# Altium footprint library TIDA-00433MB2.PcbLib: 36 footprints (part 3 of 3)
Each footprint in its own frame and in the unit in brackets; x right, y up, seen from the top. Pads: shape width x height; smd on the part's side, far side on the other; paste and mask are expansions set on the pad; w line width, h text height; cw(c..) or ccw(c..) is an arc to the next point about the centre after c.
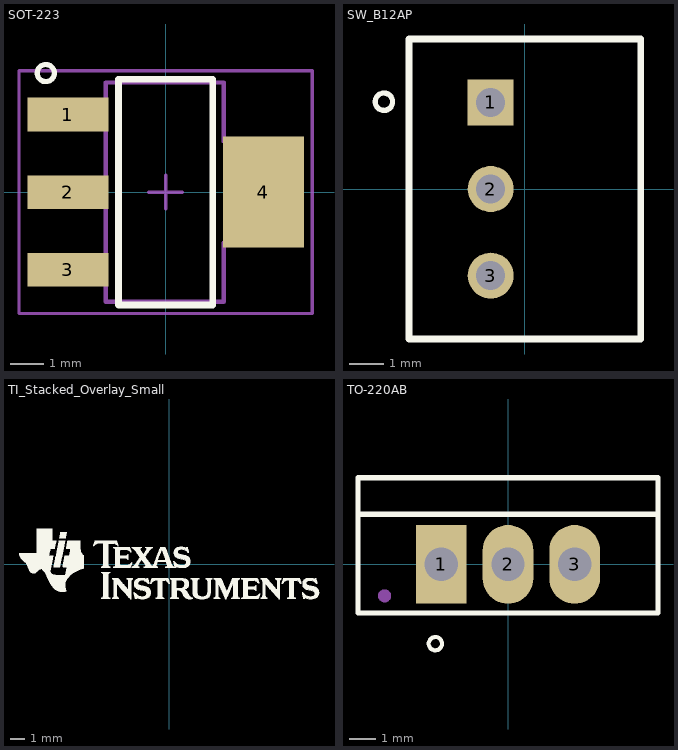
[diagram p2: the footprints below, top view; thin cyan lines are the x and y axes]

## SOT-223 [mm] "SOT223/SC73, 4-Leads, Body 6.5x3.5mm, Pitch 2.3mm, Lead Span 7mm, IPC Medium Density"
height 1.8
pads (4):
  rect 2.4x1 smd: 1(-2.9,2.3) 2(-2.9,0) 3(-2.9,-2.3)
  rect 2.4x3.3 smd: 4(2.9,0)
Top Overlay:
  circle w0.152: c-3.556,3.531 r0.254
  lines w0.2: -1.4,-3.35 -1.4,3.35 1.4,3.35 1.4,-3.35 -1.4,-3.35
Mechanical 5:
  lines w0.127: -3.525,-2.65 -3.525,-1.95 -2.797,-1.95 -2.612,-1.95 -2.374,-1.95 -2.003,-1.95 -1.775,-1.95 -1.775,-0.35 -2.003,-0.35 -2.374,-0.35 -2.612,-0.35 -2.797,-0.35 -3.525,-0.35 -3.525,0.35 -2.797,0.35 -2.612,0.35 -2.374,0.35 -2.003,0.35 -1.775,0.35 -1.775,1.95 -2.003,1.95 -2.374,1.95 -2.612,1.95 -2.797,1.95 -3.525,1.95 -3.525,2.65 -2.797,2.65 -2.612,2.65 -2.374,2.65 -2.003,2.65 -1.775,2.65 -1.775,3.25 1.725,3.25 1.725,1.5 1.953,1.5 2.324,1.5 2.562,1.5 2.747,1.5 3.475,1.5 3.475,-1.5 2.747,-1.5 2.562,-1.5 2.324,-1.5 1.953,-1.5 1.725,-1.5 1.725,-3.25 -1.775,-3.25 -1.775,-2.65 -2.003,-2.65 -2.374,-2.65 -2.612,-2.65 -2.797,-2.65 -3.525,-2.65
  text ".Designator" at -0.584,-0.432 h0.89
Mechanical 15:
  lines w0.1: -0.5,0 0.5,0 ; 0,-0.5 0,0.5 ; -4.35,-3.6 -4.35,3.6 4.35,3.6 4.35,-3.6 -4.35,-3.6
3D body: height 1.62, standoff -0.03, extent -3.5,-3.25 3.5,3.25

## SW_B12AP [mm] "NKK Switches"
height 23.1
pads (3):
  rect 1.35x1.35 hole 0.85 paste+0: 1(-1,2.54)
  round 1.35 hole 0.85 paste+0: 2(-1,0) 3(-1,-2.54)
Top Overlay:
  circle w0.152: c-4.132,2.56 r0.254
  lines w0.2: -3.4,-4.4 3.4,-4.4 3.4,4.4 -3.4,4.4 -3.4,-4.4
Mechanical 5:
  rectangle: -1.618,1.886 -0.372,3.171
  lines w0.1: -3.4,-4.4 3.4,-4.4 3.4,4.4 -3.4,4.4 -3.4,-4.4
  text ".Designator" at -2.159,-0.965 h0.89
3D body: height 22.87, standoff -3.1, extent -3.403,-4.394 3.404,4.394

## TI_Stacked_Overlay_Small [mil]
height 75
Top Overlay:
  drawing of 18 lines, arcs and shapes, not listed

## TO-220AB [mil] "Copied from Altium's version of TO3B"
height 763.78
pads (3):
  rect 76x118.11 hole 50: 1(-100,0)
  oval 76x118.11 hole 50: 2(0,0) 3(100,0)
Top Overlay:
  circle w6: c-108.99,-119 r10
  lines w7.87: -225,75 225,75 ; -225,-72.83 -225,130 225,130 225,-72.83 -225,-72.83
Mechanical 5:
  circle w9.84: c-185.04,-47.24 r4.92
  lines w5: -225,75 225,75 ; -225,-72.83 225,-72.83 225,130 -225,130 -225,-72.83
  text ".Designator" at -37.99,-127 h35
Mechanical 15:
  lines w3.94: -19.69,0 19.68,0 ; 0,-19.69 0,19.68
3D body: height 764.72, standoff -390, extent -220.72,-58.85 220.74,125.8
